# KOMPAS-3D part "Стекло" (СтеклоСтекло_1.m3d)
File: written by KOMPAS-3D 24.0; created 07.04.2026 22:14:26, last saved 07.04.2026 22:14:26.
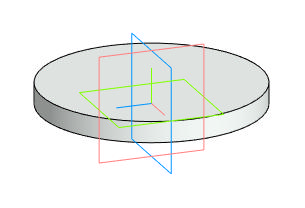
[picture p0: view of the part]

Document properties: Автор: Main; Полное имя файла: D:\DN.ru Аутсерс\Стекло смотровое DN.ru\Исходники\Стекло смотровое DN.ru SG2-34G-F тип В ГОСТ 21836-2021 Ду80 Ру16, углеродистая сталь, фланцевое\СтеклоСтекло_1.m3d

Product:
- Body: Твердое тело1  | qty 1
- Part/product: Стекло

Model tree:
1. Твердое тело1  (labels: Твердое тело1)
